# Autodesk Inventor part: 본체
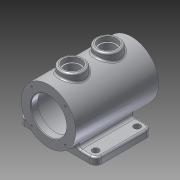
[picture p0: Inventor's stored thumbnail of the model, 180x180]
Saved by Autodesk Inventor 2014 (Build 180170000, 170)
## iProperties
Created: 2014-12
Part Number: 본체
Material: 알루미늄 6061
Document SubType Name: 판금
Designer: Owner
Mass: 1295.18 g
Surface Area: 1043.46 cm^2
Volume: 477.926 cm^3
Density: 2.71 g/cm^3
Sheet Metal Rule: 기본값
Appearance: 알루미늄 - 평지
Author: Owner
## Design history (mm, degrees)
sketch "스케치1"
  geometry: C1 r 46 at (0, 0); 1 further point
  constraints: 1 centre point, 1 coincident
  dimensions: "d0" = 92 diameter of C1
extrude "돌출1" new body sketch "스케치1" stored distance "d1" = 140; taper "d2" = 0 deg
sketch "스케치3"
  geometry: C1 r 46 at (0, 0) reference; C2 r 30 at (0, 0)
  constraints: 1 centre point, 1 coincident
  dimensions: "d6" = 60 diameter of C2
extrude "돌출3" cut sketch "스케치3" distance "d7" = 12; taper "d8" = 0 deg
sketch "스케치4"
  geometry: C1 r 30 at (0, 0) reference; C2 r 37.5 at (0, 0)
  constraints: 1 centre point, 1 coincident
  dimensions: "d9" = 75 diameter of C2
extrude "돌출4" cut sketch "스케치4" distance "d10" = 116; taper "d11" = 0 deg
sketch "스케치5"
  geometry: C1 r 46 at (0, 0) reference; C2 r 30 at (0, 0)
  constraints: 1 centre point, 1 coincident
  dimensions: "d12" = 60 diameter of C2
extrude "돌출5" cut sketch "스케치5" distance "d13" = 12; taper "d14" = 0 deg
node "작업 평면1"
sketch "스케치6"
  geometry: L1 (65, 40)-(-65, 40); L2 (-65, 40)-(-65, -55); L3 (-65, -55)-(65, -55); L4 (65, -55)-(65, 40); L5 (-46, -70)-(46, -70) reference; L6 (46, 70)-(-46, 70) reference; 3 further points
  constraints: 8 end point, 2 midpoint, 2 parallel, 2 vertical alignment, 1 horizontal, 1 perpendicular
  dimensions: "d16" = 130 distance of L2.end L3.end; "d17" = 95 distance of L1.end L2.end; "d18" = 15 vertical distance of L2.end L5.start
extrude "돌출6" join sketch "스케치6" distance "d19" = 12; taper "d20" = 0 deg
node "작업 평면2"
sketch "스케치8"
  geometry: L1 (46, 70)-(-46, 70) reference; C1 r 20 at (0, 30); C2 r 20 at (0, -30); 1 further point
  constraints: 2 centre point, 2 vertical alignment
  dimensions: "d24" = 40 distance from line of L1 C1.centre; "d25" = 40 diameter of C1; "d26" = 40 diameter of C2; "d27" = 60 distance of C1.centre C2.centre
extrude "돌출7" join sketch "스케치8" stored distance "d28" = 12; taper "d29" = 0 deg
sketch "스케치9"
  geometry: C1 r 20 at (0, 0) reference; C2 r 15 at (0, 0); 1 further point
  constraints: 1 centre point, 1 coincident
  dimensions: "d30" = 30 diameter of C2
extrude "돌출8" cut sketch "스케치9" distance "d31" = 8; taper "d32" = 0 deg
sketch "스케치10"
  geometry: C1 r 15 at (0, 0) reference; C2 r 12.5 at (0, 0); 1 further point
  constraints: 1 centre point, 1 coincident
  dimensions: "d33" = 25 diameter of C2
extrude "돌출9" cut sketch "스케치10" stored distance "d34" = 8; taper "d35" = 0 deg
sketch "스케치11"
  geometry: L1 (0, 0)-(28.284, 28.284); L2 (0, 0)-(40, 0); C1 r 46 at (0, 0) reference; 1 further point
  constraints: 4 end point, 1 coincident, 1 equal length, 1 horizontal
  dimensions: "d36" = 40 distance of L1.start L1.end; "d37" = 45 deg angle of L2 L1
hole "구멍1" sketch "스케치11" at (28.284, 28.284) diameter "d38" = 3.242; stored, may be unused: countersink angle "d42" = 90 deg, drill point angle "d44" = 118 deg; dims "d39" = 8, "d40" = 4, "d41" = 2, "d43" = 10
sketch "스케치12"
  geometry: C1 r 5.5 at (52, 27.5); 2 further points
  constraints: 1 centre point
  dimensions: "d48" = 12.5 vertical distance of point (65, 40) C1.centre; "d49" = 52 horizontal distance of C1.centre point (0, 0); "d50" = 11 diameter of C1
extrude "돌출10" cut sketch "스케치12" stored distance "d51" = 8; taper "d52" = 0 deg
sketch "스케치13"
  geometry: C1 r 5.5 at (52, 27.5) reference; C2 r 5.5 at (52, -42.5); 1 further point
  constraints: 1 centre point, 1 vertical alignment
  dimensions: "d53" = 11 diameter of C2; "d54" = 70 distance of C1.centre C2.centre
extrude "돌출11" cut sketch "스케치13" stored distance "d55" = 8; taper "d56" = 0 deg
fillet "모깎기1" dims "d57" = 10
fillet "모깎기2" dims "d58" = 5
fillet "모깎기3" dims "d59" = 3
fillet "모깎기4" dims "d60" = 3
fillet "모깎기5" dims "d61" = 3
chamfer "모따기1" distance "d62" = 1; stored, may be unused: second distance "d63" = 2, angle "d64" = 45 deg
sketch "스케치16"
  geometry: L1 (-62, -45)-(-62, 30) reference; C1 r 5.5 at (-52, 27.5) reference; 2 further points
  constraints: 1 other
  dimensions: "d65" = 35 vertical distance of point (-54, -7.5) C1.centre; "d66" = 8 distance from line of L1 point (-54, -7.5)
feature "엠보싱1" sketch "스케치16" dims "d67" = 1, "d68" = 0
fillet "모깎기6" dims "d69" = 3
node "솔리드1"
mirror "대칭1"
mirror "대칭2"
pattern_circular "원형 패턴1" dims angle "d46" = 360 deg
mirror "대칭3"
mirror "대칭4"
mirror "대칭5"
node "투영된 루프1"
other parameters: "d23" = 56, "K계수" = 4.4, "BendRadius" = 0.5 (derived), "BendReliefWidth" = 0.5 (derived), "BendReliefDepth" = 0.25 (derived), "CornerReliefSize" = 2 (derived), "SeamGap" = 0.01, "MinimumRemnant" = 1 (derived), "TransitionRadius" = 0.5 (= BendRadius)
